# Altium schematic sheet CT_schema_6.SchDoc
size 385 x 355 mm
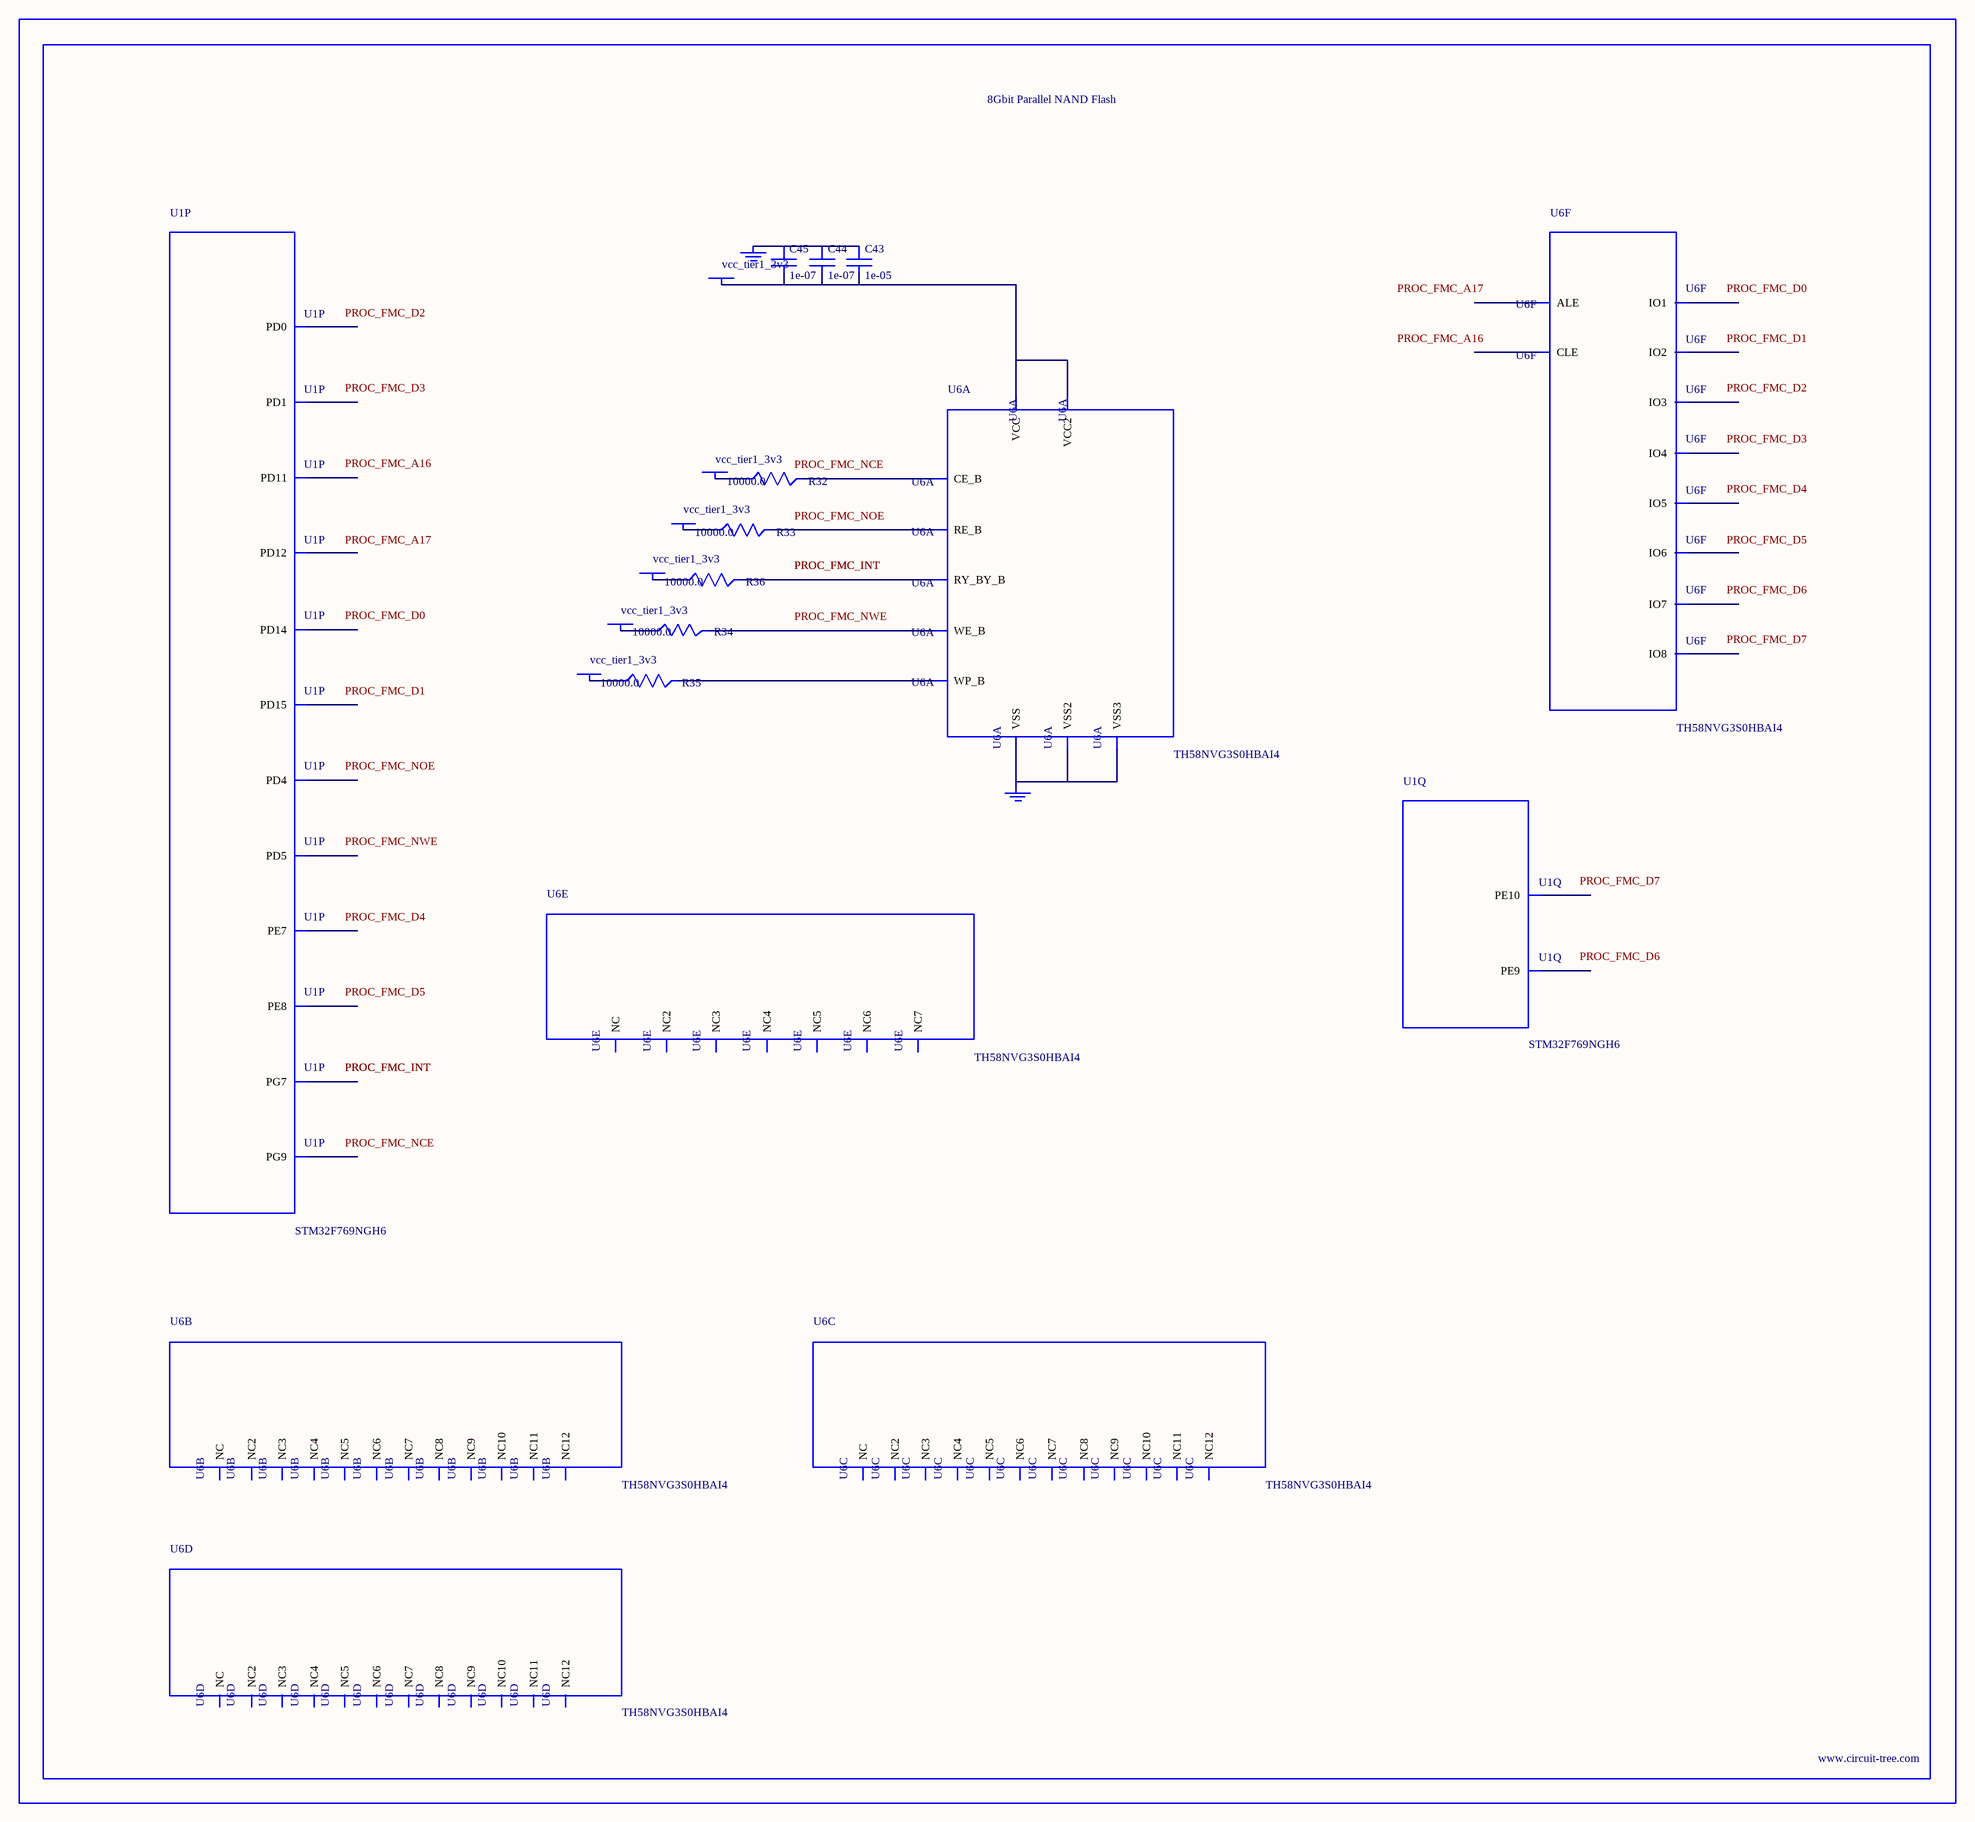
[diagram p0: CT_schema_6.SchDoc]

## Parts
BORDER5  (no value)
C43  1e-05  [C0805]
C44  1e-07  [C0402]
C45  1e-07  [C0402]
GND_INSTANCE_5_0  (no value)
GND_INSTANCE_5_1  (no value)
POWER_INSTANCE_5_0  vcc_tier1_3v3
POWER_INSTANCE_5_1  vcc_tier1_3v3
POWER_INSTANCE_5_2  vcc_tier1_3v3
POWER_INSTANCE_5_3  vcc_tier1_3v3
POWER_INSTANCE_5_4  vcc_tier1_3v3
POWER_INSTANCE_5_5  vcc_tier1_3v3
R32  10000.0  [R0603]
R33  10000.0  [R0603]
R34  10000.0  [R0603]
R35  10000.0  [R0603]
R36  10000.0  [R0603]
U1  STM32F769NGH6  [TFBGA216]  (parts P,Q of 17)
U6  TH58NVG3S0HBAI4  [TH58NVG3S0HBAI4]  (parts A,B,C,D,E,F of 6)

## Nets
NetC43_1: C43.1 C44.1 C45.1 GND_INSTANCE_5_0.0(GND)
NetC43_2: C43.2 C44.2 C45.2 POWER_INSTANCE_5_5.0(PWR) U6.H8(VCC) U6.J6(VCC2)
NetGND_INSTANCE_5_1_0: GND_INSTANCE_5_1.0(GND) U6.C5(VSS) U6.K3(VSS2) U6.K8(VSS3)
NetPOWER_INSTANCE_5_0_0: POWER_INSTANCE_5_0.0(PWR) R32.1
NetPOWER_INSTANCE_5_1_0: POWER_INSTANCE_5_1.0(PWR) R33.1
NetPOWER_INSTANCE_5_2_0: POWER_INSTANCE_5_2.0(PWR) R34.1
NetPOWER_INSTANCE_5_3_0: POWER_INSTANCE_5_3.0(PWR) R35.1
NetPOWER_INSTANCE_5_4_0: POWER_INSTANCE_5_4.0(PWR) R36.1
NetR32_2: R32.2 U6.C6(CE_B)
NetR33_2: R33.2 U6.D4(RE_B)
NetR34_2: R34.2 U6.C7(WE_B)
NetR35_2: R35.2 U6.C3(WP_B)
NetR36_2: R36.2 U6.C8(RY_BY_B)

Not connected (* = marked no-connect by the designer): U1 B12(PD0) C10(PD5) C12(PD1) D9(PG9) D11(PD4) J14(PG7) K13(PD15) L12(PD14) M10(PD12) N9(PE8) N10(PD11) P9(PE9) R8(PE7) R9(PE10); U6 A1(NC) A2(NC3) A9(NC4) A10(NC2) B1(NC5) B9(NC7) B10(NC6) C4(ALE) D3(NC8) D5(CLE) D6(NC9) D7(NC10) D8(NC11) E3(NC12) E4(NC) E5(NC2) E6(NC3) E7(NC4) E8(NC5) F3(NC6) F4(NC7) F5(NC8) F6(NC9) F7(NC10) F8(NC11) G3(NC12) G4(NC) G5(NC2) G6(NC3) G7(NC4) G8(NC5) H3(NC6) H4(IO1) H5(NC7) H6(NC8) H7(NC9) J3(NC10) J4(IO2) J5(NC11) J7(IO6) J8(IO8) K4(IO3) K5(IO4) K6(IO5) K7(IO7) L1(NC12) L2(NC2) L9(NC3) L10(NC) M1(NC4) M2(NC6) M9(NC7) M10(NC5)

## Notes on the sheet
- Labels drawn without touching a wire or pin: PROC_FMC_A16, PROC_FMC_A17, PROC_FMC_D0, PROC_FMC_D1, PROC_FMC_D2, PROC_FMC_D3, PROC_FMC_D4, PROC_FMC_D5, PROC_FMC_D6, PROC_FMC_D7, PROC_FMC_NCE, PROC_FMC_NOE, PROC_FMC_NWE

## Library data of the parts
BORDER5 = BORDER_PAGE5
C43 = C0805C106K8RACTU
C44 C45 = C0402C104K3RACTU
GND_INSTANCE_5_0 GND_INSTANCE_5_1 = GND
POWER_INSTANCE_5_0-POWER_INSTANCE_5_5 = PWR
R32-R36 = RC0603JR-0710KL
